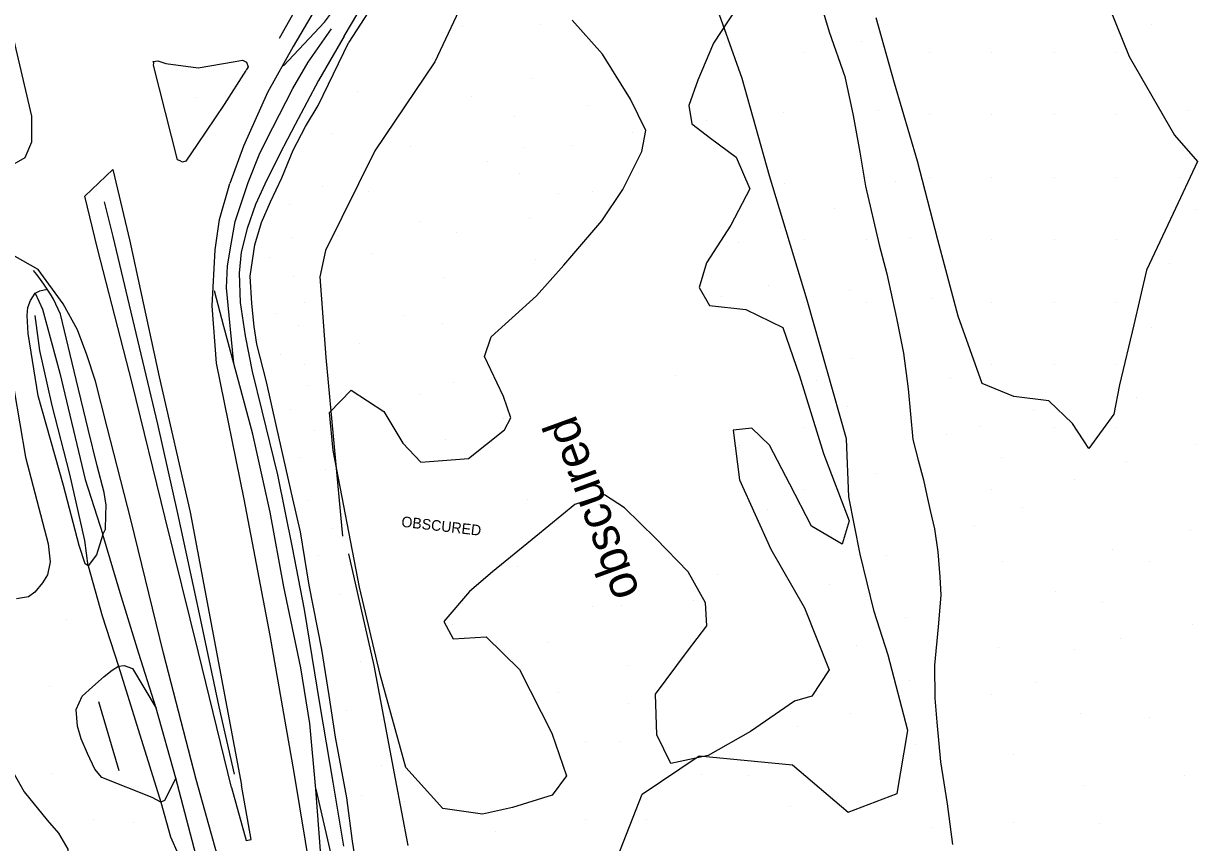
# Model space of a CAD drawing. Extents: x 524772 to 528246, y 273285 to 283088.
# Drawn here: x 526864.4 to 527033.6, y 277185.1 to 277303.2 of the extents above; entities that cross this region are included whole.
import ezdxf

# ---------------------------------------------------------------- set-up
doc = ezdxf.new("R2010")
doc.units = 0
for name, color, linetype in [('Exist DTM Crownline', 7, 'Continuous'), ('Exist DTM Spot Elevation CELL', 7, 'Continuous'), ('Exist Roads EOP', 7, 'Continuous'), ('Old_Level_12', 7, 'Continuous'), ('PH Exist DTM Breakline', 7, 'Continuous'), ('PH Exist DTM Obscure Area', 7, 'Continuous'), ('PH Exist DTM Obscure Area Text', 7, 'Continuous'), ('PH Exist DTM Point', 7, 'Continuous')]:
    doc.layers.add(name, color=color, linetype=linetype)

msp = doc.modelspace()

# ---------------------------------------------------------------- linework, layer by layer
at = {"layer": 'Exist DTM Crownline'}
msp.add_lwpolyline([(526901.35, 277301.04), (526908.81, 277314.4), (526911.35, 277318.36), (526918.66, 277331.36), (526921.35, 277335.68), (526928.61, 277348.41)], dxfattribs=at)
at = {"layer": 'Exist DTM Spot Elevation CELL'}
for p, q in [((526965.5, 277300.48), (526965.5, 277300.48)), ((526973.58, 277273.75), (526973.58, 277273.75)), ((526958.4, 277252.47), (526958.4, 277252.47)), ((526978.66, 277251.73), (526978.66, 277251.73)), ((526937.11, 277234.54), (526937.11, 277234.54)), ((526964.51, 277223.81), (526964.51, 277223.81))]:
    msp.add_line(p, q, dxfattribs=at)
at = {"layer": 'Exist Roads EOP'}
for points in [[(526930.59, 277347.23), (526923.26, 277334.58), (526920.61, 277329.93), (526913.35, 277317.21), (526910.72, 277312.56), (526903.28, 277299.87)], [(526841.95, 277274.94), (526852.49, 277277.06), (526856.72, 277278.39), (526861.05, 277281.78), (526864.65, 277283.88), (526865.61, 277286.11), (526865.65, 277289.81), (526860.92, 277309.82), (526857.04, 277325.89)], [(526903.28, 277299.87), (526899.6, 277293.22), (526896.15, 277285.48), (526894.19, 277280.09)], [(526896.49, 277296.4), (526893.37, 277291.51), (526889.44, 277285.75), (526887.82, 277283.35), (526887.36, 277283.21), (526887.03, 277283.36), (526886.62, 277283.51), (526883.16, 277297.16), (526883.23, 277297.44), (526883.14, 277297.68), (526883.8, 277297.8), (526884.93, 277297.41), (526889.58, 277296.8), (526894.94, 277297.7), (526895.97, 277297.88), (526896.58, 277297.58), (526896.83, 277296.95), (526896.5, 277296.46)], [(526880.1, 277251.34), (526875.08, 277270.76), (526873.29, 277278.31), (526877.3, 277282.13), (526879.74, 277271.81)], [(526892.26, 277254.24), (526891.63, 277262.47), (526892.05, 277270.54), (526892.68, 277274.9), (526894.19, 277280.09)], [(526900.85, 277153.48), (526896.06, 277170.16), (526889.3, 277194.22), (526884.63, 277212.43), (526879.92, 277231.7), (526876.48, 277244.99), (526874.79, 277251.63), (526873.56, 277255.42), (526872.21, 277259), (526870.14, 277262.76), (526866.56, 277267.72), (526863.21, 277269.57), (526861.12, 277271.45), (526858.18, 277272.32), (526855.9, 277272.51), (526842.82, 277270.02)], [(526879.74, 277271.81), (526883.99, 277252.26), (526888.43, 277232.76), (526895.86, 277193.41)], [(526899.97, 277214.95), (526896.21, 277234.62), (526892.26, 277254.24)], [(526894.4, 277193.06), (526889.66, 277212.5), (526884.83, 277231.91), (526880.1, 277251.34)], [(526918.39, 277116.54), (526914.05, 277136.07), (526910.19, 277155.71), (526906.72, 277175.44), (526903.44, 277195.22), (526899.97, 277214.95)], [(526894.4, 277193.06), (526896.5, 277185.4), (526897.22, 277185.56), (526895.86, 277193.41)]]:
    msp.add_lwpolyline(points, dxfattribs=at)
at = {"layer": 'Old_Level_12'}
for points in [[(526931.08, 277313.31), (526923.72, 277297.66), (526915.07, 277284.84), (526907.95, 277270.47), (526907.12, 277266.67), (526908.01, 277255.03), (526910.43, 277229.27)], [(526946.05, 277172.83), (526953.62, 277192.1), (526961.82, 277197.62), (526975.26, 277196.34), (526983.28, 277189.53), (526990.35, 277192.2), (526991.87, 277201.27), (526989.08, 277212.13), (526987.06, 277218.44), (526985, 277226.69), (526983.38, 277234.96), (526983.03, 277243.31), (526977.4, 277263.32), (526971.94, 277281.2), (526968.01, 277295.26), (526963.74, 277307.32)], [(526911.29, 277226.73), (526914.94, 277210.64), (526918, 277194.33), (526919.81, 277184.72)]]:
    msp.add_lwpolyline(points, dxfattribs=at)
at = {"layer": 'PH Exist DTM Breakline'}
for points in [[(526947.52, 277359.6), (526942.24, 277350.19), (526936.91, 277341.79), (526933.3, 277336.13), (526926.06, 277325.05), (526918.5, 277311.57), (526911.32, 277300.46)], [(526910.63, 277301.33), (526918.69, 277314.88)], [(526901.89, 277297.09), (526907.8, 277303.37), (526911.83, 277308.77), (526915.99, 277314.68)], [(526978.57, 277308.62), (526980.57, 277301.99), (526982.81, 277295.53), (526984, 277289.91), (526984.96, 277284.64), (526985.81, 277279.74), (526987.78, 277271.27), (526988.87, 277267.09), (526990.25, 277260.69), (526991.26, 277255.68), (526991.96, 277250.54), (526992.6, 277243.21), (526993.38, 277240.26), (526994.14, 277237.4), (526994.63, 277235.16), (526995.13, 277232.98), (526995.74, 277230.35), (526996.22, 277227.03), (526996.51, 277223.42), (526996.64, 277220.76), (526996.27, 277216.22), (526995.76, 277210.71), (526995.78, 277205.92), (526996.05, 277202.46), (526996.62, 277196.75), (526997.58, 277190.73), (526998.34, 277184.84)], [(526894.73, 277254.19), (526894.09, 277261.1), (526893.71, 277265.08), (526893.85, 277268.25), (526894.35, 277271.36), (526894.96, 277274.64), (526896.81, 277280.26), (526898.51, 277284.46), (526900.35, 277288.17), (526903.27, 277293.8), (526905.45, 277297.62), (526908.84, 277302.38)], [(526910.63, 277301.33), (526906.96, 277294.95), (526903.6, 277288.63), (526901.39, 277284.39), (526899.22, 277280.03), (526897.88, 277277.08), (526896.67, 277273.63), (526895.78, 277270.2), (526895.52, 277267.18), (526895.65, 277262.94), (526896.39, 277258.15), (526897.41, 277253.04), (526898.78, 277247.33), (526901.02, 277238.12), (526903.15, 277227.67), (526904.89, 277218.7), (526907.07, 277205.16), (526908.99, 277193.83), (526910.57, 277184.61)], [(526912.51, 277181.06), (526911.86, 277185.35), (526911.04, 277191.56), (526909.42, 277200.3), (526908.47, 277206.33), (526907.44, 277212.93), (526905.59, 277222.21), (526904.33, 277229.9), (526903.26, 277234.65), (526900.9, 277245.11), (526899.46, 277251.54), (526898.07, 277256.94), (526897.69, 277259.51), (526897.36, 277262.8), (526897.1, 277266.78), (526897.76, 277271.25), (526898.74, 277274.5), (526900.01, 277277.46), (526901.66, 277280.95), (526903.31, 277284.91), (526905.09, 277288.35), (526906.89, 277291.33), (526911.32, 277300.46)], [(526894.85, 277195), (526892.64, 277204.68), (526889.78, 277218.09), (526886.69, 277232.57), (526883.78, 277245.43), (526880.89, 277257.55), (526877.36, 277272.48), (526876.12, 277277.48)], [(526897.58, 277163.67), (526895.87, 277168.46), (526892.48, 277176.3), (526889.8, 277181.4), (526886.36, 277194.4), (526883.53, 277204.48), (526881.07, 277212.38), (526878.38, 277221.11), (526875.84, 277229.51), (526876.25, 277230.28), (526876.28, 277232.3), (526876.33, 277233.77), (526876.07, 277235.6), (526875.05, 277239.42), (526873.73, 277244.72), (526872.03, 277251.84), (526869.74, 277261.27), (526868.77, 277263.43), (526868.32, 277264.16), (526867.85, 277264.89), (526867.37, 277265.6), (526866.86, 277266.3), (526866.33, 277266.98), (526865.86, 277267.56)], [(526875.84, 277229.51), (526874.94, 277226.59), (526873.76, 277225), (526873.32, 277225.32), (526872.45, 277227.92), (526870.18, 277236.59), (526866.53, 277249.52), (526865.1, 277258.5), (526864.95, 277261.08), (526865.04, 277262.26), (526865.44, 277263.24), (526866.12, 277264.32), (526866.79, 277264.66), (526867.85, 277264.89)], [(526866.12, 277264.32), (526867.18, 277262.02), (526869.65, 277252.76), (526873.31, 277237.46), (526875.84, 277229.51)], [(526906.97, 277176.46), (526907.26, 277183.92), (526906.54, 277192.83), (526905.68, 277202.3), (526904.42, 277210.29), (526901.93, 277222), (526900, 277232.75), (526897.48, 277243.97), (526894.73, 277254.19), (526893.28, 277259.49), (526891.98, 277264.64)], [(526873.76, 277225), (526873.26, 277228.64), (526871.09, 277238.23), (526868.58, 277248.12), (526866.76, 277256.03), (526866.09, 277261.11)], [(526863.07, 277250.3), (526864.72, 277240.67), (526868, 277228.19), (526868.27, 277225.58), (526867.9, 277223.69), (526867.17, 277222.58), (526866.07, 277221.2), (526865.13, 277220.56), (526863.41, 277220.24)], [(526873.76, 277225), (526875.78, 277217.82), (526878.14, 277210.55)], [(526855.06, 277212.76), (526856.34, 277212.18), (526857.4, 277211.26), (526858.14, 277210.06), (526858.93, 277206.93), (526859.52, 277203.5), (526860.43, 277200.78), (526861.96, 277196.97), (526864.54, 277192.44), (526867.83, 277188.37), (526869.48, 277186.49), (526870.82, 277184.15), (526871.02, 277181.99), (526870.94, 277180.29), (526874.53, 277179.12), (526877.73, 277178.28), (526879.55, 277178.02), (526882.35, 277177.75), (526884.99, 277178.27), (526885.43, 277181.95), (526887.82, 277180.97), (526889.8, 277181.4)], [(526886.36, 277194.4), (526884.75, 277191.18), (526884.2, 277190.95), (526882.99, 277191.64), (526875.7, 277194.52), (526874.73, 277195.69), (526873.66, 277197.96), (526872.72, 277200.08), (526872.2, 277201.9), (526872.02, 277204.3), (526872.89, 277206.22), (526874.38, 277207.59), (526876.06, 277209.06), (526877.2, 277209.98), (526878.14, 277210.55), (526878.92, 277210.65), (526880.12, 277210.21), (526883.53, 277204.48)], [(526878.14, 277210.55), (526880.96, 277201.4), (526884.2, 277190.95)], [(526878.21, 277195.44), (526875.3, 277205.41)], [(526906.54, 277192.83), (526909.56, 277179.91), (526910.98, 277171.16), (526912.24, 277163.7), (526913.41, 277157.58), (526915.6, 277145.86), (526917.52, 277135.8), (526919.17, 277126.79), (526920.37, 277119.33), (526921.89, 277114.46), (526923.25, 277110.11)], [(526884.2, 277190.95), (526885.6, 277185.94), (526887.82, 277180.97)]]:
    msp.add_lwpolyline(points, dxfattribs=at)
at = {"layer": 'PH Exist DTM Obscure Area'}
for points in [[(526968.13, 277306.8), (526963.9, 277300.36), (526961.62, 277295.02), (526960.34, 277291.35), (526960.78, 277288.69), (526963.45, 277286.65), (526967.15, 277283.9), (526969.14, 277279.35), (526966.37, 277274.13), (526962.88, 277268.67), (526961.8, 277265.14), (526963.31, 277262.51), (526968.54, 277261.94), (526973.9, 277259.37), (526976.26, 277252.4), (526979.75, 277241.22), (526983.43, 277231.48), (526982.42, 277228.11), (526978.02, 277230.72), (526974.87, 277236.78), (526971.95, 277242.42), (526969.39, 277244.84), (526966.7, 277244.57), (526967.62, 277237.4), (526972.17, 277227.43), (526976.98, 277218.96), (526980.54, 277210.02), (526978.07, 277206.23), (526975.54, 277205.49), (526969.21, 277201.13), (526963.11, 277197.65), (526957.71, 277196.5), (526955.72, 277200.65), (526955.53, 277206.49), (526960.13, 277212.71), (526962.93, 277216.35), (526962.75, 277219.7), (526960.23, 277224.15), (526955.56, 277228.95), (526951.06, 277233.38), (526948.15, 277235.23), (526943.9, 277233.87), (526938.27, 277229.25), (526932.02, 277224.15), (526928.71, 277221.31), (526925.03, 277217), (526926.34, 277214.51), (526931.12, 277214.79), (526935.92, 277210.09), (526940.57, 277200.9), (526942.7, 277194.75), (526940.64, 277191.98), (526934.93, 277190.19), (526930.57, 277189.24), (526924.87, 277190.05), (526919.55, 277195.94)], [(527020.06, 277307.74), (527023.8, 277298.44), (527030.32, 277287.09), (527033.65, 277283.26)], [(526919.55, 277195.94), (526915.84, 277209.35), (526912.88, 277221.93), (526909.04, 277241.62), (526908.52, 277247.11), (526911.65, 277250.31), (526916.38, 277247.26), (526919.11, 277242.67), (526921.68, 277239.96), (526928.58, 277240.46), (526933.76, 277244.63), (526934.66, 277246.32), (526933.59, 277249.39), (526930.86, 277255.17), (526931.85, 277258.03), (526938.39, 277263.94), (526942.3, 277268.33), (526947.77, 277274.72), (526950.79, 277279.23), (526953.55, 277284.74), (526954.11, 277287.77), (526951.94, 277292.28), (526947.89, 277298.74), (526943.51, 277303.67)], [(527033.65, 277283.26), (527030.12, 277275.77), (527026.29, 277267.64), (527024.46, 277259.76), (527022.41, 277251.11), (527021.57, 277246.88), (527017.99, 277241.93), (527015.64, 277245.52), (527012.23, 277248.79), (527007.18, 277249.4), (527002.63, 277251.29), (526999.17, 277261), (526996.22, 277272), (526993.31, 277283.33), (526989.99, 277294.55), (526987.34, 277303.98)]]:
    msp.add_lwpolyline(points, dxfattribs=at)
at = {"layer": 'PH Exist DTM Point'}
for p, q in [((526938.99, 277303), (526938.99, 277303)), ((527027.02, 277303.07), (527027.02, 277303.07)), ((526927.68, 277302.7), (526927.68, 277302.7)), ((526985.28, 277300.6), (526985.28, 277300.6)), ((526923.43, 277298.07), (526923.43, 277298.07)), ((526967.52, 277298.76), (526967.52, 277298.76)), ((526977, 277299), (526977, 277299)), ((526995, 277299), (526995, 277299)), ((527003.99, 277299.01), (527003.99, 277299.01)), ((527013, 277299), (527013, 277299)), ((527022, 277299), (527022, 277299)), ((526937.76, 277295.23), (526937.76, 277295.23)), ((526912.6, 277293.42), (526912.6, 277293.42)), ((526889.39, 277292.52), (526889.39, 277292.52)), ((526928.99, 277292.61), (526928.99, 277292.61)), ((526945.91, 277291.37), (526945.91, 277291.37)), ((526935.14, 277289.71), (526935.14, 277289.71)), ((526973.97, 277290.3), (526973.97, 277290.3)), ((526987.67, 277290.69), (526987.67, 277290.69)), ((526995, 277290), (526995, 277290)), ((527004, 277290), (527004, 277290)), ((527013, 277290), (527013, 277290)), ((527022, 277290), (527022, 277290)), ((527032.37, 277290.65), (527032.37, 277290.65)), ((526962.84, 277289.13), (526962.84, 277289.13)), ((526908.82, 277287.38), (526908.82, 277287.38)), ((526952.17, 277287.52), (526952.17, 277287.52)), ((526920.21, 277285.5), (526920.21, 277285.5)), ((526936.67, 277285.34), (526936.67, 277285.34)), ((526943.41, 277285.57), (526943.41, 277285.57)), ((526931.25, 277283.35), (526931.25, 277283.35)), ((526935.91, 277281.55), (526935.91, 277281.55)), ((526986, 277281), (526986, 277281)), ((526994.98, 277281.01), (526994.98, 277281.01)), ((527004, 277281), (527004, 277281)), ((527013, 277281), (527013, 277281)), ((527022, 277281), (527022, 277281)), ((527031, 277281), (527031, 277281)), ((526907.52, 277279.74), (526907.52, 277279.74)), ((526974.11, 277280.09), (526974.11, 277280.09)), ((526990.12, 277280.37), (526990.12, 277280.37)), ((526914.11, 277278.98), (526914.11, 277278.98)), ((526941.56, 277278.66), (526941.56, 277278.66)), ((526946.49, 277278.96), (526946.49, 277278.96)), ((526902.8, 277277.14), (526902.8, 277277.14)), ((526981.38, 277276.55), (526981.38, 277276.55)), ((527033.3, 277276.31), (527033.3, 277276.31)), ((526921.45, 277274.68), (526921.45, 277274.68)), ((526937.3, 277275.03), (526937.3, 277275.03)), ((526909.63, 277272.6), (526909.63, 277272.6)), ((526926.86, 277273.03), (526926.86, 277273.03)), ((526903.06, 277272.28), (526903.06, 277272.28)), ((526967.49, 277271.58), (526967.49, 277271.58)), ((526977, 277272), (526977, 277272)), ((526986, 277272.01), (526986, 277272.01)), ((526992.33, 277272.31), (526992.33, 277272.31)), ((527004, 277272), (527004, 277272)), ((527013, 277272), (527013, 277272)), ((527022, 277272), (527022, 277272)), ((526899.84, 277269.48), (526899.84, 277269.48)), ((526914.68, 277270.01), (526914.68, 277270.01)), ((526938.29, 277269.15), (526938.29, 277269.15)), ((527029.63, 277268.59), (527029.63, 277268.59)), ((526903.33, 277266.69), (526903.33, 277266.69)), ((526925.02, 277266.59), (526925.02, 277266.59)), ((526971.76, 277265.36), (526971.76, 277265.36)), ((526983.52, 277264.7), (526983.52, 277264.7)), ((526904.99, 277263), (526904.99, 277263)), ((526965.04, 277263.85), (526965.04, 277263.85)), ((526977, 277263), (526977, 277263)), ((526986, 277263), (526986, 277263)), ((526995.26, 277263.5), (526995.26, 277263.5)), ((527004, 277263), (527004, 277263)), ((527013, 277263), (527013, 277263)), ((527022, 277263), (527022, 277263)), ((526900.68, 277261.37), (526900.68, 277261.37)), ((526919.13, 277261.02), (526919.13, 277261.02)), ((526904, 277259.6), (526904, 277259.6)), ((526924.88, 277259.94), (526924.88, 277259.94)), ((527026.95, 277259.41), (527026.95, 277259.41)), ((526912.86, 277257.07), (526912.86, 277257.07)), ((526901.48, 277255.44), (526901.48, 277255.44)), ((526904.99, 277254), (526904.99, 277254)), ((526983.8, 277254.92), (526983.8, 277254.92)), ((527004, 277254), (527004, 277254)), ((527013, 277254), (527013, 277254)), ((527022, 277254), (527022, 277254)), ((526905.46, 277250.94), (526905.46, 277250.94)), ((526926.46, 277251.5), (526926.46, 277251.5)), ((526998.09, 277252.02), (526998.09, 277252.02)), ((526921.61, 277249.68), (526921.61, 277249.68)), ((527024.87, 277249.27), (527024.87, 277249.27)), ((526902.94, 277247.48), (526902.94, 277247.48)), ((526983.26, 277248.01), (526983.26, 277248.01)), ((527009.95, 277247.42), (527009.95, 277247.42)), ((526933.58, 277246.31), (526933.58, 277246.31)), ((526906.43, 277244.5), (526906.43, 277244.5)), ((526976.96, 277244.99), (526976.96, 277244.99)), ((526997.5, 277243.99), (526997.5, 277243.99)), ((527002.37, 277245.09), (527002.37, 277245.09)), ((527013, 277245), (527013, 277245)), ((527022, 277245), (527022, 277245)), ((526925.22, 277243.16), (526925.22, 277243.16)), ((526967.63, 277242.41), (526967.63, 277242.41)), ((527033.56, 277242.46), (527033.56, 277242.46)), ((526904.42, 277240.64), (526904.42, 277240.64)), ((527005.44, 277240.6), (527005.44, 277240.6)), ((526907.96, 277238.83), (526907.96, 277238.83)), ((527023.43, 277240.06), (527023.43, 277240.06)), ((526987.44, 277238.38), (526987.44, 277238.38)), ((527015.94, 277237.47), (527015.94, 277237.47)), ((526977, 277236), (526977, 277236)), ((527004, 277236), (527004, 277236)), ((526905.54, 277234.46), (526905.54, 277234.46)), ((526947.25, 277233.79), (526947.25, 277233.79)), ((526971.73, 277233.16), (526971.73, 277233.16)), ((527008.37, 277233.42), (527008.37, 277233.42)), ((526908.98, 277230.34), (526908.98, 277230.34)), ((527001.49, 277230.84), (527001.49, 277230.84)), ((527032.59, 277230.1), (527032.59, 277230.1)), ((527021.44, 277227.36), (527021.44, 277227.36)), ((526907, 277226.47), (526907, 277226.47)), ((526951.53, 277226.79), (526951.53, 277226.79)), ((526988.84, 277226.48), (526988.84, 277226.48)), ((527005.54, 277225.58), (527005.54, 277225.58)), ((527026.71, 277225.63), (527026.71, 277225.63)), ((526935.7, 277224.88), (526935.7, 277224.88)), ((526980.59, 277222.37), (526980.59, 277222.37)), ((526910.06, 277220.93), (526910.06, 277220.93)), ((526960.93, 277220.03), (526960.93, 277220.03)), ((527013.11, 277221.28), (527013.11, 277221.28)), ((526946.37, 277219.21), (526946.37, 277219.21)), ((526950.61, 277219.27), (526950.61, 277219.27)), ((527020.01, 277219.78), (527020.01, 277219.78)), ((526870.58, 277217.31), (526870.58, 277217.31)), ((526977, 277218), (526977, 277218)), ((526991.56, 277217.57), (526991.56, 277217.57)), ((526926.28, 277216.51), (526926.28, 277216.51)), ((527032.96, 277216.5), (527032.96, 277216.5)), ((526939.96, 277213.9), (526939.96, 277213.9)), ((526984.52, 277213.53), (526984.52, 277213.53)), ((527004.98, 277213.28), (527004.98, 277213.28)), ((527022.56, 277214.52), (527022.56, 277214.52)), ((527015.97, 277212.91), (527015.97, 277212.91)), ((526912.95, 277211.15), (526912.95, 277211.15)), ((526951.57, 277210.7), (526951.57, 277210.7)), ((526992.12, 277208.47), (526992.12, 277208.47)), ((526868.24, 277207.62), (526868.24, 277207.62)), ((526941.61, 277206.8), (526941.61, 277206.8)), ((527010.45, 277208.16), (527010.45, 277208.16)), ((526951.57, 277205.23), (526951.57, 277205.23)), ((527004.01, 277206.47), (527004.01, 277206.47)), ((526910.94, 277204.19), (526910.94, 277204.19)), ((526983.6, 277203.76), (526983.6, 277203.76)), ((527016.81, 277203.71), (527016.81, 277203.71)), ((527026.7, 277203.11), (527026.7, 277203.11)), ((526916.02, 277202.85), (526916.02, 277202.85)), ((526975.98, 277201.79), (526975.98, 277201.79)), ((526945.41, 277199.75), (526945.41, 277199.75)), ((526950.54, 277199.69), (526950.54, 277199.69)), ((526993.01, 277199.23), (526993.01, 277199.23)), ((527007.13, 277197.8), (527007.13, 277197.8)), ((526868.43, 277195.13), (526868.43, 277195.13)), ((526916.04, 277196.25), (526916.04, 277196.25)), ((526962.22, 277194.92), (526962.22, 277194.92)), ((526968.9, 277194.83), (526968.9, 277194.83)), ((527031.74, 277194.82), (527031.74, 277194.82)), ((527017.43, 277193.28), (527017.43, 277193.28)), ((526913.2, 277191.85), (526913.2, 277191.85)), ((526919.36, 277191.01), (526919.36, 277191.01)), ((526975, 277190.28), (526975, 277190.28)), ((526874.46, 277188.49), (526874.46, 277188.49)), ((526880.33, 277188.05), (526880.33, 277188.05)), ((526945.46, 277188.39), (526945.46, 277188.39)), ((526954.21, 277188.4), (526954.21, 277188.4)), ((527007.12, 277188.06), (527007.12, 277188.06)), ((527019.51, 277187.89), (527019.51, 277187.89)), ((526932.51, 277186.78), (526932.51, 277186.78)), ((526995.36, 277187.32), (526995.36, 277187.32))]:
    msp.add_line(p, q, dxfattribs=at)

# ---------------------------------------------------------------- texts
at = {"layer": 'Old_Level_12'}
msp.add_text('obscured', height=5, rotation=110, dxfattribs=at).set_placement((526953.31, 277221.13))
at = {"layer": 'PH Exist DTM Obscure Area Text'}
msp.add_text('OBSCURED', height=1.524, rotation=353.4693, dxfattribs=at).set_placement((526918.83, 277230.65))

doc.saveas('drawing.dxf')
